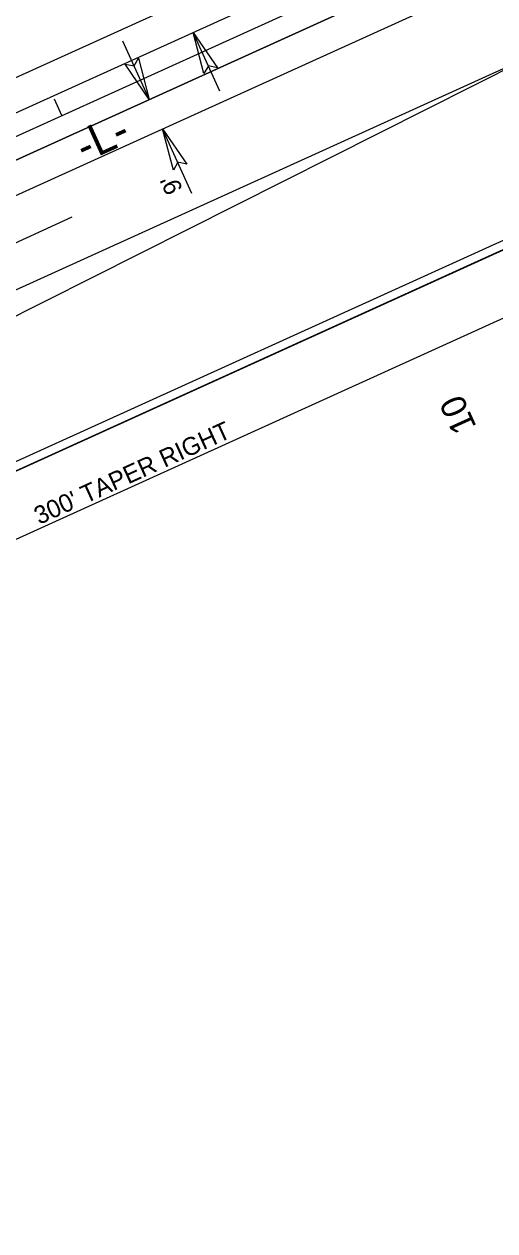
# Model space of a CAD drawing. Extents: x 2242984 to 2250974, y 661492 to 664681.
# Drawn here: x 2249311.2 to 2249442.6, y 663220.6 to 663557.7 of the extents above; entities that cross this region are included whole.
import ezdxf

# ---------------------------------------------------------------- set-up
doc = ezdxf.new("R2010")
doc.units = 0
for name, color, linetype in [('Prop Conc Shoulder Berm Gutter', 7, 'Continuous'), ('Prop Dimension', 7, 'Continuous'), ('Prop Dimension Text', 7, 'Continuous'), ('Prop EOT', 7, 'Continuous'), ('Prop Guardrail', 7, 'Continuous'), ('Prop Horizontal Alignment', 7, 'Continuous'), ('Prop Horizontal Alignment Curve and Spiral Data', 7, 'Continuous'), ('Prop Horizontal Alignment Tick Label', 7, 'Continuous'), ('Prop Horizontal Alignment Tick Small', 7, 'Continuous'), ('Prop Lane Lines', 7, 'Continuous'), ('Prop Paved Shoulder', 7, 'Continuous'), ('Scratch_Level_6', 7, 'Continuous'), ('Scratch_Level_8', 7, 'Continuous'), ('Typical Terminator CELL', 7, 'Continuous')]:
    doc.layers.add(name, color=color, linetype=linetype)

# ---------------------------------------------------------------- blocks, each defined once
blk = doc.blocks.new('TERMINATOR')
at = {"layer": 'Typical Terminator CELL'}
blk.add_lwpolyline([(-0.469, 0.081), (0, 0), (-0.471, -0.083), (-0.411, 0)], close=True, dxfattribs=at)

msp = doc.modelspace()

# ---------------------------------------------------------------- linework, layer by layer
at = {"layer": 'Prop Conc Shoulder Berm Gutter'}
msp.add_line((2249183.08, 663378.4), (2249474.15, 663510.62), dxfattribs=at)
at = {"layer": 'Prop Dimension'}
for p, q in [((2249365.85, 663539), (2249358.39, 663555.42)), ((2249338.67, 663553.1), (2249346.13, 663536.68)), ((2249358.05, 663510.43), (2249349.85, 663528.48)), ((2249482.48, 663492.62), (2249209.34, 663368.55))]:
    msp.add_line(p, q, dxfattribs=at)
at = {"layer": 'Prop EOT'}
for p, q in [((2248200.21, 663039.2), (2249433.89, 663599.6)), ((2248212.61, 663011.89), (2249446.3, 663572.29)), ((2249188.04, 663415.44), (2249456.22, 663550.44))]:
    msp.add_line(p, q, dxfattribs=at)
at = {"layer": 'Prop Guardrail'}
for p, q in [((2249182.68, 663475.61), (2249637.91, 663682.4)), ((2249642.88, 663671.47), (2249233.17, 663485.36)), ((2249182.68, 663475.61), (2249592.39, 663661.72)), ((2249167.75, 663368.88), (2249475.25, 663508.56))]:
    msp.add_line(p, q, dxfattribs=at)
at = {"layer": 'Prop Horizontal Alignment'}
msp.add_line((2247500.8, 662705.02), (2249793.08, 663746.29), dxfattribs=at)
at = {"layer": 'Prop Horizontal Alignment Tick Small'}
msp.add_line((2249321.73, 663532.18), (2249319.66, 663536.73), dxfattribs=at)
at = {"layer": 'Prop Lane Lines'}
for p, q in [((2248759.04, 663233.74), (2249456.25, 663550.45)), ((2249280.02, 663483.58), (2249324.65, 663503.85))]:
    msp.add_line(p, q, dxfattribs=at)
at = {"layer": 'Prop Paved Shoulder'}
for p, q in [((2248894.79, 663344.83), (2249437.63, 663591.42)), ((2248895.78, 663332.1), (2249442.57, 663580.48)), ((2249184.04, 663376.28), (2249475.25, 663508.56))]:
    msp.add_line(p, q, dxfattribs=at)
at = {"layer": 'Scratch_Level_6'}
msp.add_line((2249167.72, 663368.76), (2249475.29, 663508.47), dxfattribs=at)
at = {"layer": 'Scratch_Level_8'}
msp.add_line((2249172.45, 663370.91), (2249475.29, 663508.48), dxfattribs=at)

# ---------------------------------------------------------------- block references
at = {"layer": 'Prop Dimension', "xscale": 25}
for p, yscale, rotation in [((2249358.39, 663555.42), 25.00000000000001, 114.43012589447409), ((2249346.13, 663536.68), 25, -65.56987410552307), ((2249349.85, 663528.48), 25, 114.43012589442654)]:
    msp.add_blockref('TERMINATOR', p, dxfattribs=dict(at, yscale=yscale, rotation=rotation))

# ---------------------------------------------------------------- texts
at = {"layer": 'Prop Dimension'}
msp.add_text("9'", height=5, rotation=114.4301, dxfattribs=at).set_placement((2249355.59, 663511.55))
at = {"layer": 'Prop Dimension Text'}
msp.add_text("300' TAPER RIGHT", height=5, rotation=24.4979, dxfattribs=at).set_placement((2249315.41, 663417.8))
at = {"layer": 'Prop Horizontal Alignment Curve and Spiral Data'}
msp.add_text('-L-', height=9, rotation=24.4301, dxfattribs=at).set_placement((2249328.05, 663518.97))
at = {"layer": 'Prop Horizontal Alignment Tick Label'}
msp.add_text('10', height=7, rotation=114.4301, dxfattribs=at).set_placement((2249437.58, 663445.23))

doc.saveas('drawing.dxf')
